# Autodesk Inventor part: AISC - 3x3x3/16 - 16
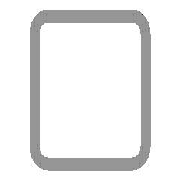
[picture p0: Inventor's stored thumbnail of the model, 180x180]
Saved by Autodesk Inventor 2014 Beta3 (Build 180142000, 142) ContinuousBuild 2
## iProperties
_CCFamilyMember: 9
_CCFamilyDisplayName: ANSI AISC (Square) - Tube
_FrameMemberDoc: Frame Member File
_Version: 15.0.0
_GetPNFromCC: 1
Created: 2010-11
Part Number: AISC - 3x3x3/16 - 16
Material: Steel, Mild
Description: Tube
Document SubType Name: Modeling
Standard: ANSI
Designer: Beta-8540w
Standards Organization: ANSI
Language: en-US
Size Designation: 3x3x3/16
Categories: <MemberInstance><Categories><Category DisplayName="Structural Shapes" InternalName="089c4875-fa83-4c05-b084-43b9cc11f5ed" Mnemonic="GRDR"><CategoryParameter Dis
Stock Number: 3x3x3/16
Density: 7.86 g/cm^3
Appearance: Steel
IsCustomPart: 1
G_L: 16.000 in
G_W: 3.000 in
G_H: 3.000 in
Author: Beta-8540w
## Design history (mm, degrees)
node "Start plane"
node "End plane"
sketch "Sketch"
  geometry: L1 (-38.1, -28.575)-(-38.1, 28.575); L2 (-28.575, 38.1)-(28.575, 38.1); L3 (38.1, 28.575)-(38.1, -28.575); L4 (28.575, -38.1)-(-28.575, -38.1); L5 (-28.575, 33.337)-(28.575, 33.338); L6 (33.338, 28.575)-(33.338, -28.575); L7 (28.575, -33.337)-(-28.575, -33.338); L8 (-33.338, -28.575)-(-33.338, 28.575); L9 (0, 56.102)-(0, -56.102) reference; L10 (-56.102, 0)-(56.102, 0) reference; A1 r 9.525 centre (-28.575, -28.575) between (-38.1, -28.575) and (-28.575, -38.1); A2 r 9.525 centre (-28.575, 28.575) between (-28.575, 38.1) and (-38.1, 28.575); A3 r 9.525 centre (28.575, 28.575) between (38.1, 28.575) and (28.575, 38.1); A4 r 9.525 centre (28.575, -28.575) between (28.575, -38.1) and (38.1, -28.575); A5 r 4.763 centre (-28.575, 28.575) between (-28.575, 33.337) and (-33.338, 28.575); A6 r 4.763 centre (28.575, 28.575) between (33.338, 28.575) and (28.575, 33.338); A7 r 4.763 centre (28.575, -28.575) between (28.575, -33.337) and (33.338, -28.575); A8 r 4.763 centre (-28.575, -28.575) between (-33.338, -28.575) and (-28.575, -33.338)
  constraints: 16 end point, 16 point on circle, 8 centre point, 8 tangent, 4 parallel, 3 equal radius, 2 perpendicular, 7 other
  dimensions: "d10" = 76.2 distance between parallel lines of L2 L4 (= G_H); "d11" = 76.2 distance between parallel lines of L1 L3 (= G_W); "d12" = 4.7625 distance between parallel lines of L3 L6 (= G_T); "d15" = 38.1 distance between parallel lines of L2 L10 (= 0.5 x d10); "d16" = 38.1 distance between parallel lines of L9 L3 (= 0.5 x d11); "d17" = 9.525 radius of A1 (= G_IR)
extrude "Body" new body sketch "Sketch" stored distance "d3" = 406.4 (= G_L); taper "d4" = 0 deg
node "Driven Length"
  sketch "Sketch3"
    geometry: L1 (0, 0)-(10, 0) reference
    constraints: 2 end point, 1 horizontal
  workplane "Work Plane3"
  sketch "Sketch4"
    geometry: L1 (-2, -114.3)-(12, -114.3) reference; L2 (-2, 292.1)-(12, 292.1) reference
    dimensions: "d19" = 406.4 distance between parallel lines of L1 L2 (derived)
workplane "Work Plane4"
split "Split1"
body "Solid1"
other parameters: "G_W" = 76.2 [user parameter; used in 1 equation term], "G_H" = 76.2 [user parameter; used in 1 equation term], "G_T" = 4.7625 [user parameter; used in 1 equation term], "G_IR" = 9.525 [user parameter; used in 1 equation term], "G_L" = 406.4 (= d19) [user parameter; used in 1 equation term], "G_OFFSET_START" = 114.3 [user parameter; used in 1 equation term], "G_OFFSET_END" = 38.1 [user parameter; used in 1 equation term], "d13" = -114.3 (= -G_OFFSET_START), "d14" = 292.1 (= G_OFFSET_END + B_L), "B_L" = 254 [user parameter; used in 1 equation term], "d18" = 90 deg
